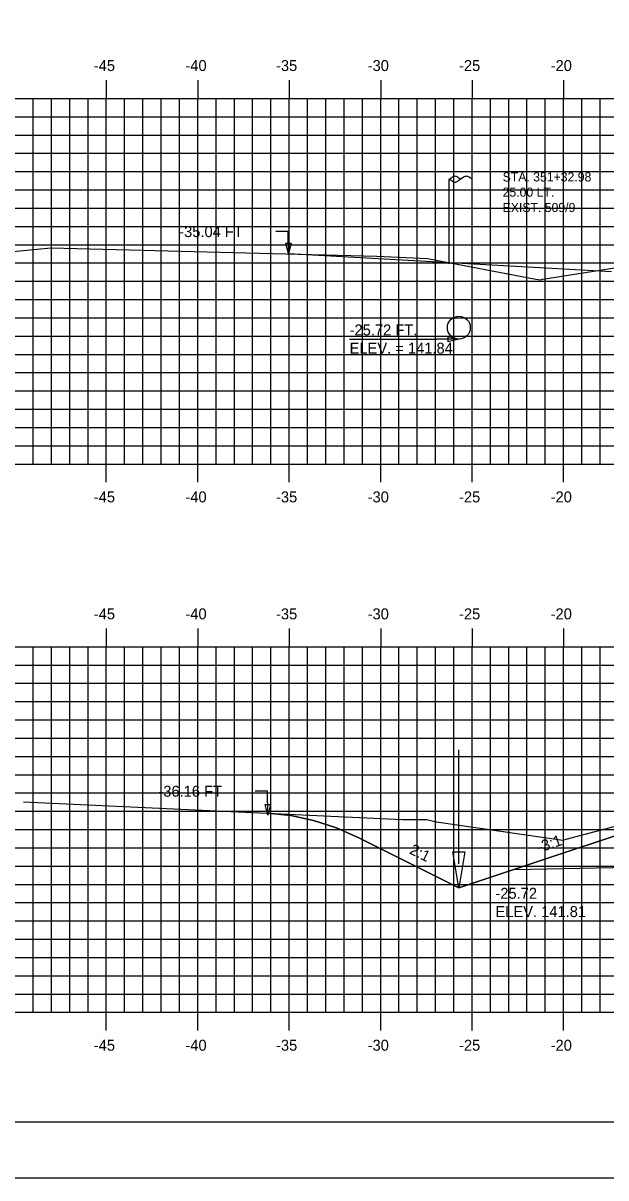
# Model space of a CAD drawing. Extents: x 1144751 to 1144921, y 608981 to 609091.
# Drawn here: x 1144784.1 to 1144815.9, y 608981.3 to 609044.5 of the extents above; entities that cross this region are included whole.
import ezdxf

# ---------------------------------------------------------------- set-up
doc = ezdxf.new("R2010")
doc.units = 0
for name, color, linetype in [('ANNOTATION', 7, 'Continuous'), ('BORDER', 7, 'Continuous'), ('D_Drainage_Culvert', 7, 'Continuous'), ('D_Drainage_Ditch_Line', 7, 'Continuous'), ('D_Roadway_SlopeLines', 7, 'Continuous'), ('D_Roadway_SubGrade', 7, 'Continuous'), ('D_Text_Monospaced', 7, 'Continuous'), ('D_Text_Standard', 7, 'Continuous'), ('H_V ANNOTATION', 7, 'Continuous'), ('MAJOR', 7, 'Continuous'), ('MINOR', 7, 'Continuous'), ('PLOT BOUNDARY', 7, 'Continuous'), ('S_Roadway_Centerline', 7, 'Continuous'), ('S_Utilities_Pole_Power', 7, 'Continuous')]:
    doc.layers.add(name, color=color, linetype=linetype)

msp = doc.modelspace()

# ---------------------------------------------------------------- linework, layer by layer
msp.add_lwpolyline([(1144797.455, 609001.234), (1144798.705, 609001.105), (1144799.955, 609000.834), (1144801.205, 609000.422), (1144802.455, 608999.868), (1144807.894, 608997.148), (1144810.894, 608998.148), (1144818.618, 609000.723), (1144818.619, 609000.723), (1144822.619, 609000.883), (1144833.619, 609001.103), (1144844.619, 609000.883), (1144848.619, 609000.723), (1144856.342, 608998.148), (1144859.342, 608997.148), (1144861.625, 608998.29), (1144862.875, 608998.836), (1144864.125, 608999.226), (1144865.375, 608999.458), (1144866.625, 608999.533)])
at = {"layer": 'BORDER'}
msp.add_lwpolyline([(1144758.619, 608984.335), (1144918.619, 608984.335), (1144918.619, 609089.335), (1144758.619, 609089.335)], close=True, dxfattribs=at)
at = {"layer": 'D_Drainage_Culvert'}
msp.add_circle((1144807.894, 609027.796), 0.625, dxfattribs=at)
at = {"layer": 'D_Drainage_Ditch_Line'}
msp.add_line((1144807.894, 608998.461), (1144807.895, 609004.704), dxfattribs=at)
msp.add_lwpolyline([(1144807.566, 608999.117), (1144808.222, 608999.117), (1144807.894, 608997.148)], close=True, dxfattribs=at)
at = {"layer": 'D_Roadway_SlopeLines'}
msp.add_line((1144816.245, 609030.841), (1144798.576, 609031.83), dxfattribs=at)
for points in [[(1144807.894, 608997.148), (1144802.455, 608999.868), (1144801.205, 609000.422), (1144799.955, 609000.834), (1144798.705, 609001.105), (1144797.455, 609001.234)], [(1144810.894, 608998.148), (1144807.894, 608997.148)]]:
    msp.add_lwpolyline(points, dxfattribs=at)
at = {"layer": 'D_Roadway_SubGrade'}
msp.add_lwpolyline([(1144822.619, 609000.466), (1144822.619, 609000.633), (1144818.619, 609000.473), (1144818.619, 609000.723), (1144818.618, 609000.723), (1144810.894, 608998.148), (1144822.619, 608998.383)], close=True, dxfattribs=at)
at = {"layer": 'D_Text_Standard'}
msp.add_line((1144801.922, 609027.171), (1144806.679, 609027.171), dxfattribs=at)
for points in [[(1144798.576, 609031.83), (1144798.569, 609033.05), (1144797.889, 609033.05)], [(1144807.894, 609027.171), (1144807.359, 609027.171), (1144806.679, 609027.171)], [(1144797.455, 609001.118), (1144797.441, 609002.431), (1144796.761, 609002.431)]]:
    msp.add_lwpolyline(points, dxfattribs=at)
for points in [[(1144798.576, 609031.83), (1144798.427, 609032.411), (1144798.718, 609032.413)], [(1144807.894, 609027.171), (1144807.312, 609027.026), (1144807.312, 609027.317)], [(1144797.455, 609001.118), (1144797.303, 609001.698), (1144797.594, 609001.702)]]:
    msp.add_lwpolyline(points, close=True, dxfattribs=at)
at = {"layer": 'MAJOR'}
for p, q in [((1144788.619, 609041.337), (1144788.619, 609040.335)), ((1144793.619, 609041.337), (1144793.619, 609040.335)), ((1144798.619, 609041.337), (1144798.619, 609040.335)), ((1144803.619, 609041.337), (1144803.619, 609040.335)), ((1144808.619, 609041.337), (1144808.619, 609040.335)), ((1144813.619, 609041.337), (1144813.619, 609040.335)), ((1144763.619, 609040.335), (1144903.619, 609040.335)), ((1144763.619, 609040.335), (1144903.619, 609040.335)), ((1144788.619, 609020.335), (1144788.619, 609040.335)), ((1144793.619, 609020.335), (1144793.619, 609040.335)), ((1144798.619, 609020.335), (1144798.619, 609040.335)), ((1144803.619, 609020.335), (1144803.619, 609040.335)), ((1144808.619, 609020.335), (1144808.619, 609040.335)), ((1144813.619, 609020.335), (1144813.619, 609040.335)), ((1144763.619, 609035.335), (1144903.619, 609035.335)), ((1144763.619, 609030.335), (1144903.619, 609030.335)), ((1144763.619, 609025.335), (1144903.619, 609025.335)), ((1144763.619, 609020.335), (1144903.619, 609020.335)), ((1144763.619, 609020.335), (1144903.619, 609020.335)), ((1144788.619, 609019.333), (1144788.619, 609020.335)), ((1144793.619, 609019.333), (1144793.619, 609020.335)), ((1144798.619, 609019.333), (1144798.619, 609020.335)), ((1144803.619, 609019.333), (1144803.619, 609020.335)), ((1144808.619, 609019.333), (1144808.619, 609020.335)), ((1144813.619, 609019.333), (1144813.619, 609020.335)), ((1144788.619, 609011.337), (1144788.619, 609010.335)), ((1144793.619, 609011.337), (1144793.619, 609010.335)), ((1144798.619, 609011.337), (1144798.619, 609010.335)), ((1144803.619, 609011.337), (1144803.619, 609010.335)), ((1144808.619, 609011.337), (1144808.619, 609010.335)), ((1144813.619, 609011.337), (1144813.619, 609010.335)), ((1144763.619, 609010.335), (1144903.619, 609010.335)), ((1144763.619, 609010.335), (1144903.619, 609010.335)), ((1144788.619, 608990.335), (1144788.619, 609010.335)), ((1144793.619, 608990.335), (1144793.619, 609010.335)), ((1144798.619, 608990.335), (1144798.619, 609010.335)), ((1144803.619, 608990.335), (1144803.619, 609010.335)), ((1144808.619, 608990.335), (1144808.619, 609010.335)), ((1144813.619, 608990.335), (1144813.619, 609010.335)), ((1144763.619, 609005.335), (1144903.619, 609005.335)), ((1144763.619, 609000.335), (1144903.619, 609000.335)), ((1144763.619, 608995.335), (1144903.619, 608995.335)), ((1144763.619, 608990.335), (1144903.619, 608990.335)), ((1144763.619, 608990.335), (1144903.619, 608990.335)), ((1144788.619, 608989.333), (1144788.619, 608990.335)), ((1144793.619, 608989.333), (1144793.619, 608990.335)), ((1144798.619, 608989.333), (1144798.619, 608990.335)), ((1144803.619, 608989.333), (1144803.619, 608990.335)), ((1144808.619, 608989.333), (1144808.619, 608990.335)), ((1144813.619, 608989.333), (1144813.619, 608990.335))]:
    msp.add_line(p, q, dxfattribs=at)
at = {"layer": 'MINOR'}
for p, q in [((1144784.619, 609020.335), (1144784.619, 609040.335)), ((1144785.619, 609020.335), (1144785.619, 609040.335)), ((1144786.619, 609020.335), (1144786.619, 609040.335)), ((1144787.619, 609020.335), (1144787.619, 609040.335)), ((1144789.619, 609020.335), (1144789.619, 609040.335)), ((1144790.619, 609020.335), (1144790.619, 609040.335)), ((1144791.619, 609020.335), (1144791.619, 609040.335)), ((1144792.619, 609020.335), (1144792.619, 609040.335)), ((1144794.619, 609020.335), (1144794.619, 609040.335)), ((1144795.619, 609020.335), (1144795.619, 609040.335)), ((1144796.619, 609020.335), (1144796.619, 609040.335)), ((1144797.619, 609020.335), (1144797.619, 609040.335)), ((1144799.619, 609020.335), (1144799.619, 609040.335)), ((1144800.619, 609020.335), (1144800.619, 609040.335)), ((1144801.619, 609020.335), (1144801.619, 609040.335)), ((1144802.619, 609020.335), (1144802.619, 609040.335)), ((1144804.619, 609020.335), (1144804.619, 609040.335)), ((1144805.619, 609020.335), (1144805.619, 609040.335)), ((1144806.619, 609020.335), (1144806.619, 609040.335)), ((1144807.619, 609020.335), (1144807.619, 609040.335)), ((1144809.619, 609020.335), (1144809.619, 609040.335)), ((1144810.619, 609020.335), (1144810.619, 609040.335)), ((1144811.619, 609020.335), (1144811.619, 609040.335)), ((1144812.619, 609020.335), (1144812.619, 609040.335)), ((1144814.619, 609020.335), (1144814.619, 609040.335)), ((1144815.619, 609020.335), (1144815.619, 609040.335)), ((1144763.619, 609039.335), (1144903.619, 609039.335)), ((1144763.619, 609038.335), (1144903.619, 609038.335)), ((1144763.619, 609037.335), (1144903.619, 609037.335)), ((1144763.619, 609036.335), (1144903.619, 609036.335)), ((1144763.619, 609034.335), (1144903.619, 609034.335)), ((1144763.619, 609033.335), (1144903.619, 609033.335)), ((1144763.619, 609032.335), (1144903.619, 609032.335)), ((1144763.619, 609031.335), (1144903.619, 609031.335)), ((1144763.619, 609029.335), (1144903.619, 609029.335)), ((1144763.619, 609028.335), (1144903.619, 609028.335)), ((1144763.619, 609027.335), (1144903.619, 609027.335)), ((1144763.619, 609026.335), (1144903.619, 609026.335)), ((1144763.619, 609024.335), (1144903.619, 609024.335)), ((1144763.619, 609023.335), (1144903.619, 609023.335)), ((1144763.619, 609022.335), (1144903.619, 609022.335)), ((1144763.619, 609021.335), (1144903.619, 609021.335)), ((1144784.619, 608990.335), (1144784.619, 609010.335)), ((1144785.619, 608990.335), (1144785.619, 609010.335)), ((1144786.619, 608990.335), (1144786.619, 609010.335)), ((1144787.619, 608990.335), (1144787.619, 609010.335)), ((1144789.619, 608990.335), (1144789.619, 609010.335)), ((1144790.619, 608990.335), (1144790.619, 609010.335)), ((1144791.619, 608990.335), (1144791.619, 609010.335)), ((1144792.619, 608990.335), (1144792.619, 609010.335)), ((1144794.619, 608990.335), (1144794.619, 609010.335)), ((1144795.619, 608990.335), (1144795.619, 609010.335)), ((1144796.619, 608990.335), (1144796.619, 609010.335)), ((1144797.619, 608990.335), (1144797.619, 609010.335)), ((1144799.619, 608990.335), (1144799.619, 609010.335)), ((1144800.619, 608990.335), (1144800.619, 609010.335)), ((1144801.619, 608990.335), (1144801.619, 609010.335)), ((1144802.619, 608990.335), (1144802.619, 609010.335)), ((1144804.619, 608990.335), (1144804.619, 609010.335)), ((1144805.619, 608990.335), (1144805.619, 609010.335)), ((1144806.619, 608990.335), (1144806.619, 609010.335)), ((1144807.619, 608990.335), (1144807.619, 609010.335)), ((1144809.619, 608990.335), (1144809.619, 609010.335)), ((1144810.619, 608990.335), (1144810.619, 609010.335)), ((1144811.619, 608990.335), (1144811.619, 609010.335)), ((1144812.619, 608990.335), (1144812.619, 609010.335)), ((1144814.619, 608990.335), (1144814.619, 609010.335)), ((1144815.619, 608990.335), (1144815.619, 609010.335)), ((1144763.619, 609009.335), (1144903.619, 609009.335)), ((1144763.619, 609008.335), (1144903.619, 609008.335)), ((1144763.619, 609007.335), (1144903.619, 609007.335)), ((1144763.619, 609006.335), (1144903.619, 609006.335)), ((1144763.619, 609004.335), (1144903.619, 609004.335)), ((1144763.619, 609003.335), (1144903.619, 609003.335)), ((1144763.619, 609002.335), (1144903.619, 609002.335)), ((1144763.619, 609001.335), (1144903.619, 609001.335)), ((1144763.619, 608999.335), (1144903.619, 608999.335)), ((1144763.619, 608998.335), (1144903.619, 608998.335)), ((1144763.619, 608997.335), (1144903.619, 608997.335)), ((1144763.619, 608996.335), (1144903.619, 608996.335)), ((1144763.619, 608994.335), (1144903.619, 608994.335)), ((1144763.619, 608993.335), (1144903.619, 608993.335)), ((1144763.619, 608992.335), (1144903.619, 608992.335)), ((1144763.619, 608991.335), (1144903.619, 608991.335))]:
    msp.add_line(p, q, dxfattribs=at)
at = {"layer": 'PLOT BOUNDARY'}
msp.add_lwpolyline([(1144750.526, 608981.276), (1144920.526, 608981.276), (1144920.526, 609091.276), (1144750.526, 609091.276)], close=True, dxfattribs=at)
at = {"layer": 'S_Roadway_Centerline'}
for points in [[(1144783.338, 609031.937), (1144785.588, 609032.156), (1144803.411, 609031.709), (1144806.171, 609031.584), (1144812.1, 609030.451), (1144812.366, 609030.413), (1144812.487, 609030.445), (1144817.107, 609031.177), (1144819.29, 609031.161), (1144819.463, 609031.18), (1144820.262, 609031.19), (1144830.751, 609031.377), (1144840.894, 609030.911), (1144841.691, 609030.885), (1144841.859, 609030.863), (1144846.068, 609030.451), (1144846.347, 609030.396), (1144849.307, 609029.907), (1144849.614, 609029.914), (1144853.774, 609030.361), (1144875.416, 609029.679), (1144877.702, 609029.675)], [(1144784.091, 609001.855), (1144804.815, 609000.892), (1144806.118, 609000.876), (1144806.664, 609000.752), (1144813.58, 608999.76), (1144813.762, 608999.807), (1144816.936, 609000.648), (1144817.059, 609000.66), (1144819.398, 609000.91), (1144820.085, 609000.917), (1144830.699, 609001.046), (1144841.624, 609000.698), (1144842.406, 609000.678), (1144842.648, 609000.652), (1144844.954, 609000.353), (1144845.157, 609000.264), (1144849.049, 608999.486), (1144849.52, 608999.482), (1144853.374, 608999.568), (1144879.018, 608999.501), (1144882.968, 608999.398)]]:
    msp.add_lwpolyline(points, dxfattribs=at)
at = {"layer": 'S_Utilities_Pole_Power'}
for p, q in [((1144807.369, 609035.915), (1144807.525, 609036.025)), ((1144807.837, 609036.025), (1144807.994, 609035.915)), ((1144808.15, 609036.025), (1144807.994, 609035.915)), ((1144808.619, 609035.915), (1144808.463, 609036.025)), ((1144807.369, 609031.295), (1144807.372, 609035.915)), ((1144807.525, 609035.804), (1144807.369, 609035.915)), ((1144807.994, 609035.915), (1144807.837, 609035.804)), ((1144808.619, 609031.295), (1144808.622, 609035.915))]:
    msp.add_line(p, q, dxfattribs=at)
for centre, start, end in [((1144807.681, 609035.804), 90, 125.26439), ((1144807.681, 609035.804), 54.73561, 90), ((1144808.306, 609035.804), 90, 125.26439), ((1144808.306, 609035.804), 54.73561, 90), ((1144807.681, 609036.025), 234.73561, 270), ((1144807.681, 609036.025), 270, 305.26439)]:
    msp.add_arc(centre, 0.271, start, end, dxfattribs=at)

# ---------------------------------------------------------------- texts
at = {"layer": 'ANNOTATION'}
for s, rotation, p in [('-3:1', 18.43482, (1144812.273, 608999.062)), ('2:1', 333.43495, (1144805.142, 608999.043))]:
    msp.add_text(s, height=0.6, rotation=rotation, dxfattribs=at).set_placement(p)
at = {"layer": 'D_Text_Monospaced'}
for s, height, p in [('STA. 351+32.98', 0.49998, (1144810.286, 609035.793)), ('25.00 LT.', 0.5, (1144810.286, 609034.959)), ('EXIST. 509/9', 0.49998, (1144810.286, 609034.119))]:
    msp.add_text(s, height=height, dxfattribs=at).set_placement(p)
at = {"layer": 'D_Text_Standard'}
for s, p in [('-35.04 FT', (1144792.606, 609032.75)), ('-25.72 FT.', (1144801.922, 609027.371)), ('ELEV. = 141.84', (1144801.922, 609026.371)), ('-36.16 FT', (1144791.467, 609002.131)), ('-25.72', (1144809.894, 608996.548)), ('ELEV. 141.81', (1144809.894, 608995.546))]:
    msp.add_text(s, height=0.6, dxfattribs=at).set_placement(p)
at = {"layer": 'H_V ANNOTATION'}
for s, p in [('-45', (1144787.937, 609041.835)), ('-40', (1144792.945, 609041.835)), ('-35', (1144797.899, 609041.835)), ('-30', (1144802.907, 609041.835)), ('-25', (1144807.904, 609041.835)), ('-20', (1144812.912, 609041.835)), ('-45', (1144787.937, 609018.235)), ('-40', (1144792.945, 609018.235)), ('-35', (1144797.899, 609018.235)), ('-30', (1144802.907, 609018.235)), ('-25', (1144807.904, 609018.235)), ('-20', (1144812.912, 609018.235)), ('-45', (1144787.937, 609011.835)), ('-40', (1144792.945, 609011.835)), ('-35', (1144797.899, 609011.835)), ('-30', (1144802.907, 609011.835)), ('-25', (1144807.904, 609011.835)), ('-20', (1144812.912, 609011.835)), ('-45', (1144787.937, 608988.235)), ('-40', (1144792.945, 608988.235)), ('-35', (1144797.899, 608988.235)), ('-30', (1144802.907, 608988.235)), ('-25', (1144807.904, 608988.235)), ('-20', (1144812.912, 608988.235))]:
    msp.add_text(s, height=0.6, dxfattribs=at).set_placement(p)

doc.saveas('drawing.dxf')
